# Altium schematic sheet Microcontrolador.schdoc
size 316 x 210 mm
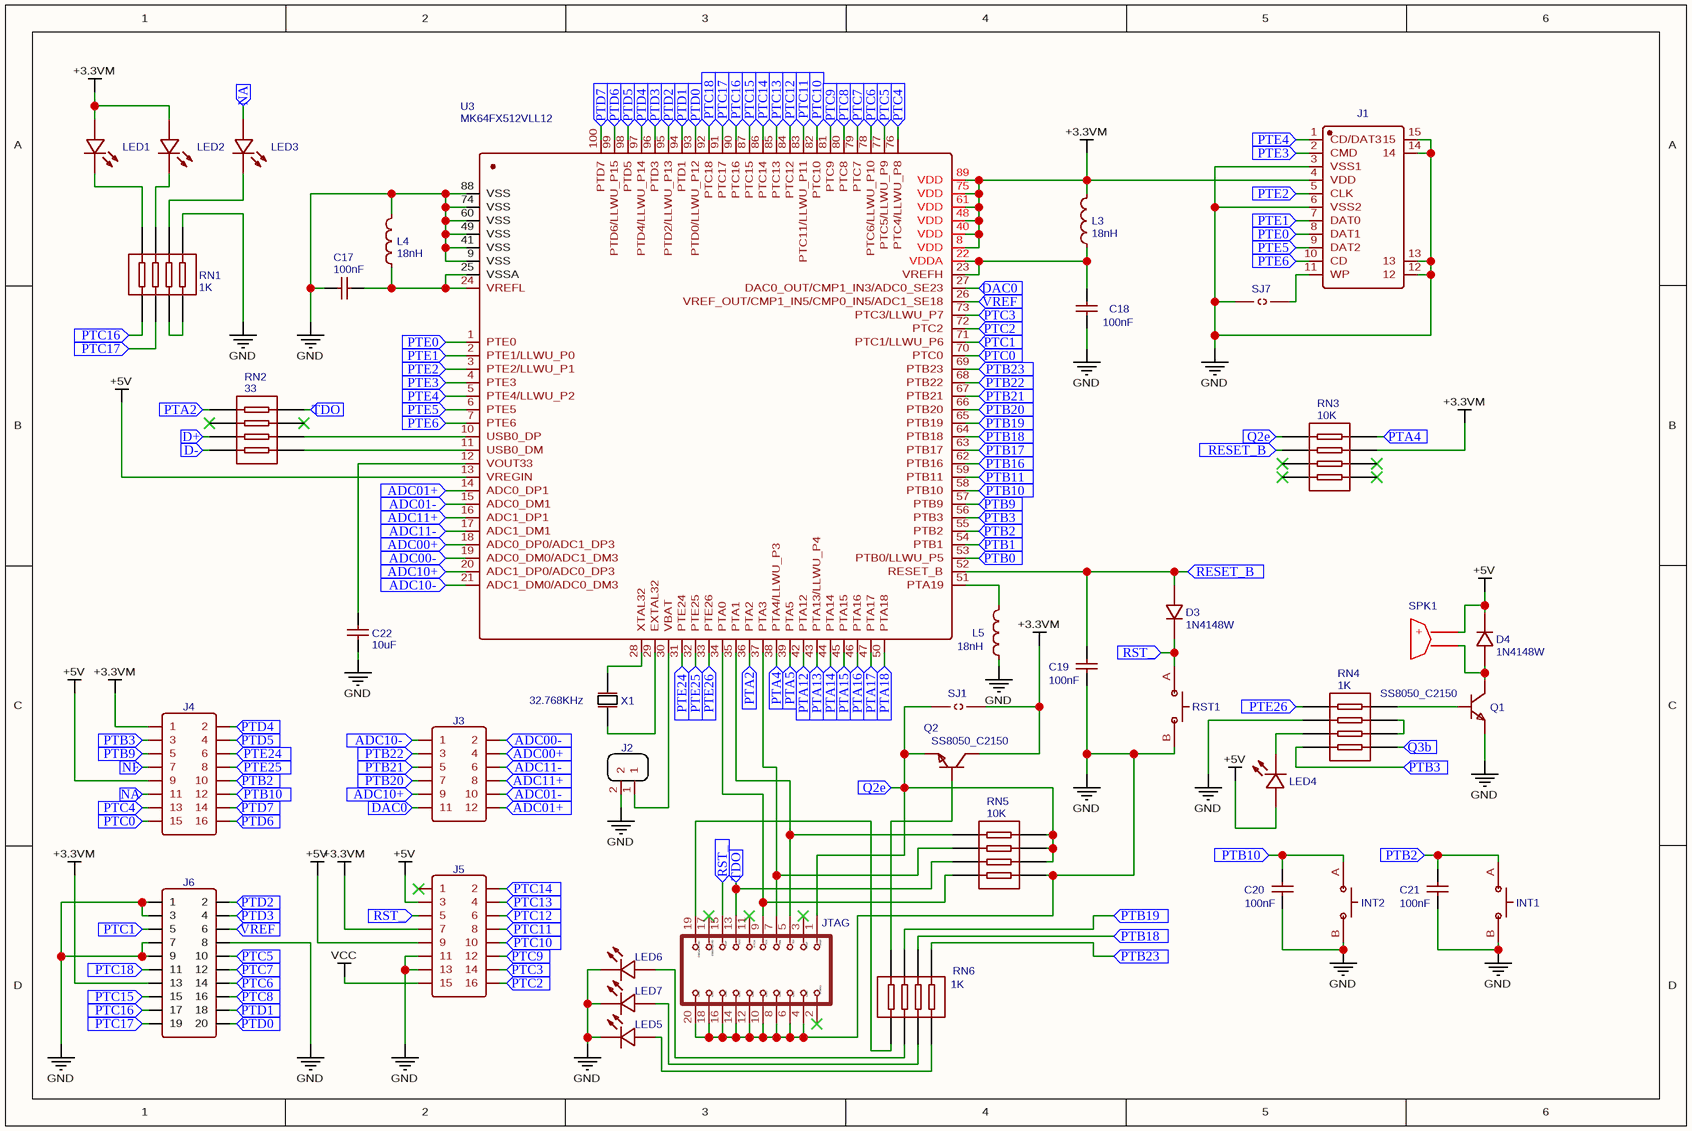
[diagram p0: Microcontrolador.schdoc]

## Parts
C17  100nF  [C0402]
C18  100nF  [C0402]
C19  100nF  [C0402]
C20  100nF  [C0402]
C21  100nF  [C0402]
C22  10uF  [C0805]
D3  1N4148W  [SOD-123_L2.8-W1.8-LS3.7-RD]
D4  1N4148W  [SOD-123_L2.8-W1.8-LS3.7-RD]
INT1  1TS002B-2500-4300 SMD Push  [SW-SMD-3.5X6X4.3-A]  (value not drawn)
INT2  1TS002B-2500-4300 SMD Push  [SW-SMD-3.5X6X4.3-A]  (value not drawn)
J1  HYC12-SD11-275  [SD-SMD_HYC12-SD11-275]  (value not drawn)
J2  53047-02  [MOLEX_53047-0210_2PIN_VERT]  (value not drawn)
J3  HEADER-FEMALE-2.54_2X6 COPY  [HDR-TH_12P-P2.54-V-R2-C6-S2.54]  (value not drawn)
J4  Header-Female-2.54_2x8  [HDR-TH_16P-P2.54-V-R2-C8-S2.54]  (value not drawn)
J5  Header-Female-2.54_2x8  [HDR-TH_16P-P2.54-V-R2-C8-S2.54]  (value not drawn)
J6  HEADER-FEMALE-2.54_2X10  [HDR-TH_20P-P2.54-V-R2-C10-S2.54]  (value not drawn)
JTAG1  JTAG  [2X10_2.54MM_PTH]
L3  18nH  [L0402]
L4  18nH  [L0402]
L5  18nH  [L0402]
LED1  XL-0805QBC  [LED0805-RD]  (value not drawn)
LED2  XL-0805QBC  [LED0805-RD]  (value not drawn)
LED3  XL-0805QBC  [LED0805-RD]  (value not drawn)
LED4  XL-0805QBC  [LED0805-RD]  (value not drawn)
LED5  0603White light_C2290  [LED0603-R-RD]  (value not drawn)
LED6  0603White light_C2290  [LED0603-R-RD]  (value not drawn)
LED7  0603White light_C2290  [LED0603-R-RD]  (value not drawn)
Q1  SS8050_C2150  [SOT-23-3_L2.9-W1.3-P1.90-LS2.4-BR]
Q2  SS8050_C2150  [SOT-23-3_L2.9-W1.3-P1.90-LS2.4-BR]
RN1  1K  [RES-ARRAY-SMD_0402-8P-L2.0-W1.0-BL]
RN2  33  [RES-ARRAY-SMD_0402-8P-L2.0-W1.0-BL]
RN3  10K  [RES-ARRAY-SMD_0402-8P-L2.0-W1.0-BL]
RN4  1K  [RES-ARRAY-SMD_0402-8P-L2.0-W1.0-BL]
RN5  10K  [RES-ARRAY-SMD_0402-8P-L2.0-W1.0-BL]
RN6  1K  [RES-ARRAY-SMD_0402-8P-L2.0-W1.0-BL]
RST1  1TS002B-2500-4300 SMD Push  [SW-SMD-3.5X6X4.3-A]  (value not drawn)
SJ1  JUMPER-PAD-2-NO  [PAD-JUMPER-2-NO_NO_SILK]  (value not drawn)
SJ7  JUMPER-PAD-2-NO  [PAD-JUMPER-2-NO_NO_SILK]  (value not drawn)
SPK1  BUZZER  [BUZZER]  (value not drawn)
U3  MK64FX512VLL12  [LQFP-100_14X14X05P]
X1  32.768KHz  [OSC-TH_BD2.0-P0.70-D0.3]

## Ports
ADC00+ (in), ADC00- (in), ADC01+ (in), ADC01- (in), ADC10+ (in), ADC10- (in), ADC11+ (in), ADC11- (in), D+ (in), D- (in), DAC0 (in), NA (in), NF (in), PTA2 (in), PTA4 (in), PTA5 (in), PTA12 (in), PTA13 (in), PTA14 (in), PTA15 (in), PTA16 (in), PTA17 (in), PTA18 (in), PTB0 (in), PTB1 (in), PTB2 (in), PTB3 (in), PTB9 (in), PTB10 (in), PTB11 (in), PTB16 (in), PTB17 (in), PTB18 (in), PTB19 (in), PTB20 (in), PTB21 (in), PTB22 (in), PTB23 (in), PTC0 (in), PTC1 (in), PTC2 (in), PTC3 (in), PTC4 (in), PTC5 (in), PTC6 (in), PTC7 (in), PTC8 (in), PTC9 (in), PTC10 (in), PTC11 (in), PTC12 (in), PTC13 (in), PTC14 (in), PTC15 (in), PTC16 (in), PTC17 (in), PTC18 (in), PTD0 (in), PTD1 (in), PTD2 (in), PTD3 (in), PTD4 (in), PTD5 (in), PTD6 (in), PTD7 (in), PTE0 (in), PTE1 (in), PTE2 (in), PTE3 (in), PTE4 (in), PTE5 (in), PTE6 (in), PTE24 (in), PTE25 (in), PTE26 (in), Q2e (in), Q3b (in), RESET_B (in), RST_ (in), TDO (in), VREF (in)

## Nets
+3.3VM: J1.4(VDD) J4.1 J5.7 J6.13 L3.2 LED1.2(A) LED2.2(A) Q2.3(C) RN3.7 SJ1.2 U3.8(VDD) U3.40(VDD) U3.48(VDD) U3.61(VDD) U3.75(VDD) U3.89(VDD)
+5V: D4.1(K) J4.9 J5.3 J5.9 LED4.2(A) SPK1.1(+) U3.13(VREGIN)
GND: C17.2 C18.1 C19.1 C20.1 C21.1 C22.1 INT1.B INT2.B J1.3(VSS1) J1.6(VSS2) J1.12 J1.13 J1.14 J1.15 J2.2 J5.11 J5.13 J6.1 J6.3 J6.7 J6.8 J6.9 JTAG1.4 JTAG1.6 JTAG1.8 JTAG1.10 JTAG1.12 JTAG1.14 JTAG1.16 JTAG1.18 JTAG1.20 L4.2 L5.1 LED5.2(K) LED6.2(K) LED7.2(K) Q1.2(E) RN1.5 RN4.6 RN5.5 RST1.B SJ7.1 U3.9(VSS) U3.41(VSS) U3.49(VSS) U3.60(VSS) U3.74(VSS) U3.88(VSS)
VCC: J5.15
ADC00+: J3.4 U3.18(ADC0_DP0/ADC1_DP3) ; port ADC00+
ADC00-: J3.2 U3.19(ADC0_DM0/ADC1_DM3) ; port ADC00-
ADC01+: J3.12 U3.14(ADC0_DP1) ; port ADC01+
ADC01-: J3.10 U3.15(ADC0_DM1) ; port ADC01-
ADC10+: J3.9 U3.20(ADC1_DP0/ADC0_DP3) ; port ADC10+
ADC10-: J3.1 U3.21(ADC1_DM0/ADC0_DM3) ; port ADC10-
ADC11+: J3.8 U3.16(ADC1_DP1) ; port ADC11+
ADC11-: J3.6 U3.17(ADC1_DM1) ; port ADC11-
D+: RN2.3 ; port D+
D-: RN2.4 ; port D-
DAC0: J3.11 U3.27(DAC0_OUT/CMP1_IN3/ADC0_SE23) ; port DAC0
NA: J4.11 LED3.2(A) ; port NA
NF: J4.7 ; port NF
PTA2: RN2.1 U3.36(PTA2) ; port PTA2
PTA4: RN3.8 U3.38(PTA4/LLWU_P3) ; port PTA4
PTA5: U3.39(PTA5) ; port PTA5
PTA12: U3.42(PTA12) ; port PTA12
PTA13: U3.43(PTA13/LLWU_P4) ; port PTA13
PTA14: U3.44(PTA14) ; port PTA14
PTA15: U3.45(PTA15) ; port PTA15
PTA16: U3.46(PTA16) ; port PTA16
PTA17: U3.47(PTA17) ; port PTA17
PTA18: U3.50(PTA18) ; port PTA18
PTB0: U3.53(PTB0/LLWU_P5) ; port PTB0
PTB1: U3.54(PTB1) ; port PTB1
PTB2: C21.2 INT1.A J4.10 U3.55(PTB2) ; port PTB2
PTB3: J4.3 RN4.8 U3.56(PTB3) ; port PTB3
PTB9: J4.5 U3.57(PTB9) ; port PTB9
PTB10: C20.2 INT2.A J4.12 U3.58(PTB10) ; port PTB10
PTB11: U3.59(PTB11) ; port PTB11
PTB16: U3.62(PTB16) ; port PTB16
PTB17: U3.63(PTB17) ; port PTB17
PTB18: RN6.2 U3.64(PTB18) ; port PTB18
PTB19: RN6.3 U3.65(PTB19) ; port PTB19
PTB20: J3.7 U3.66(PTB20) ; port PTB20
PTB21: J3.5 U3.67(PTB21) ; port PTB21
PTB22: J3.3 U3.68(PTB22) ; port PTB22
PTB23: RN6.1 U3.69(PTB23) ; port PTB23
PTC0: J4.15 U3.70(PTC0) ; port PTC0
PTC1: J6.5 U3.71(PTC1/LLWU_P6) ; port PTC1
PTC2: J5.16 U3.72(PTC2) ; port PTC2
PTC3: J5.14 U3.73(PTC3/LLWU_P7) ; port PTC3
PTC4: J4.13 U3.76(PTC4/LLWU_P8) ; port PTC4
PTC5: J6.10 U3.77(PTC5/LLWU_P9) ; port PTC5
PTC6: J6.14 U3.78(PTC6/LLWU_P10) ; port PTC6
PTC7: J6.12 U3.79(PTC7) ; port PTC7
PTC8: J6.16 U3.80(PTC8) ; port PTC8
PTC9: J5.12 U3.81(PTC9) ; port PTC9
PTC10: J5.10 U3.82(PTC10) ; port PTC10
PTC11: J5.8 U3.83(PTC11/LLWU_P11) ; port PTC11
PTC12: J5.6 U3.84(PTC12) ; port PTC12
PTC13: J5.4 U3.85(PTC13) ; port PTC13
PTC14: J5.2 U3.86(PTC14) ; port PTC14
PTC15: J6.15 U3.87(PTC15) ; port PTC15
PTC16: J6.17 RN1.1 U3.90(PTC16) ; port PTC16
PTC17: J6.19 RN1.2 U3.91(PTC17) ; port PTC17
PTC18: J6.11 U3.92(PTC18) ; port PTC18
PTD0: J6.20 U3.93(PTD0/LLWU_P12) ; port PTD0
PTD1: J6.18 U3.94(PTD1) ; port PTD1
PTD2: J6.2 U3.95(PTD2/LLWU_P13) ; port PTD2
PTD3: J6.4 U3.96(PTD3) ; port PTD3
PTD4: J4.2 U3.97(PTD4/LLWU_P14) ; port PTD4
PTD5: J4.4 U3.98(PTD5) ; port PTD5
PTD6: J4.16 U3.99(PTD6/LLWU_P15) ; port PTD6
PTD7: J4.14 U3.100(PTD7) ; port PTD7
PTE0: J1.8(DAT1) U3.1(PTE0) ; port PTE0
PTE1: J1.7(DAT0) U3.2(PTE1/LLWU_P0) ; port PTE1
PTE2: J1.5(CLK) U3.3(PTE2/LLWU_P1) ; port PTE2
PTE3: J1.2(CMD) U3.4(PTE3) ; port PTE3
PTE4: J1.1(CD/DAT3) U3.5(PTE4/LLWU_P2) ; port PTE4
PTE5: J1.9(DAT2) U3.6(PTE5) ; port PTE5
PTE6: J1.10(CD) U3.7(PTE6) ; port PTE6
PTE24: J4.6 U3.31(PTE24) ; port PTE24
PTE25: J4.8 U3.32(PTE25) ; port PTE25
PTE26: RN4.5 U3.33(PTE26) ; port PTE26
Q2e: JTAG1.1 Q2.2(E) RN3.1 RN5.6 RN5.7 RN5.8 SJ1.1 ; port Q2e
Q3b: RN4.1 ; port Q3b
RESET_B: C19.2 D3.2(A) RN3.2 U3.52(RESET_B) ; port RESET_B
RST_: D3.1(K) J5.5 JTAG1.15 RST1.A ; port RST_
TDO: JTAG1.13 RN2.8 RN5.3 ; port TDO
VREF: J6.6 U3.26(VREF_OUT/CMP1_IN5/CMP0_IN5/ADC1_SE18) ; port VREF
NetC17_1: C17.1 L4.1 U3.24(VREFL) U3.25(VSSA)
NetC18_2: C18.2 L3.1 U3.22(VDDA) U3.23(VREFH)
NetC22_2: C22.2 U3.12(VOUT33)
NetD4_2: D4.2(A) Q1.3(C) SPK1.2
NetJ1_11: J1.11(WP) SJ7.2
NetJ2_1: J2.1 U3.30(VBAT)
NetJTAG1_5: JTAG1.5 RN5.1 U3.35(PTA1)
NetJTAG1_7: JTAG1.7 RN5.2 U3.37(PTA3)
NetJTAG1_9: JTAG1.9 RN5.4 U3.34(PTA0)
NetJTAG1_19: JTAG1.19 RN6.5
NetL5_2: L5.2 U3.51(PTA19)
NetLED1_1: LED1.1(K) RN1.8
NetLED2_1: LED2.1(K) RN1.7
NetLED3_1: LED3.1(K) RN1.6
NetLED4_1: LED4.1(K) RN4.7
NetLED5_1: LED5.1(A) RN6.8
NetLED6_1: LED6.1(A) RN6.6
NetLED7_1: LED7.1(A) RN6.7
NetQ1_1: Q1.1(B) RN4.4
NetQ2_1: Q2.1(B) RN6.4
NetRN1_3: RN1.3 RN1.4
NetRN2_5: RN2.5 U3.11(USB0_DM)
NetRN2_6: RN2.6 U3.10(USB0_DP)
NetRN4_2: RN4.2 RN4.3
NetU3_28: U3.28(XTAL32) X1.1(OSC1)
NetU3_29: U3.29(EXTAL32) X1.2(OSC2)

Not connected (* = marked no-connect by the designer): J5 1*; JTAG1 2* 3* 11* 17*; RN2 2* 7*; RN3 3* 4* 5* 6*

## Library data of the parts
C17-C21 = 100nF: BOM_Manufacturer Part: CL05B104KO5NNNC; BOM_Manufacturer: SAMSUNG; nameAlias: Capacitance; SMT Type: Basic; BOM_Paste Type: base
C22 = 10uF: BOM_Manufacturer Part: CL21A106KAYNNNE; BOM_Manufacturer: SAMSUNG; nameAlias: Capacitance; SMT Type: Basic; BOM_Paste Type: base
D3 D4 = 1N4148W: BOM_Manufacturer: SEMTECH; SMT Type: Basic; BOM_Paste Type: base
INT1 INT2 RST1 = 1TS002B-2500-4300 SMD Push: BOM_Manufacturer: HYP; Contributor: LCSC; Package Display: No
J1 = HYC12-SD11-275: BOM_Manufacturer: 华宇创; Contributor: LCSC; Package Display: No
J2 = 53047-02: Contributor: SunWoo_Lim; Package Display: No
J3 = HEADER-FEMALE-2.54_2X6 COPY: BOM_Manufacturer: BOOMELE; Package Display: No
J4 J5 = Header-Female-2.54_2x8: BOM_Manufacturer: BOOMELE; BOM_Manufacturer Part: 2.54mm,2×8Double female header; Contributor: sandiko; Package Display: No
J6 = HEADER-FEMALE-2.54_2X10: BOM_Manufacturer: BOOMELE; BOM_Manufacturer Part: 2.54mm,2×10Double row female; Package Display: No
JTAG1 = JTAG: description: JTAG 20 Pin Programming Connector; Contributor: PatternAgents; Package Display: No
L3-L5 = 18nH: BOM_Manufacturer: Sunlord; BOM_Manufacturer Part: SDCL1005C18NJTDF; nameAlias: Inductance; SMT Type: Basic; BOM_Paste Type: base
LED1-LED4 = XL-0805QBC: BOM_Manufacturer: KENTO; SMT Type: Basic; BOM_Paste Type: base; Package Display: No
LED5-LED7 = 0603White light_C2290: BOM_Manufacturer: KENTO; SMT Type: Basic; BOM_Paste Type: base; Package Display: No
Q1 Q2 = SS8050_C2150: BOM_Manufacturer: CJ; BOM_Manufacturer Part: SS8050; SMT Type: Basic; BOM_Assembly Type: smtWeld; BOM_Paste Type: base
RN1 RN4 RN6 = 1K: BOM_Manufacturer: UniOhm; BOM_Manufacturer Part: 4D02WGJ0102TCE; nameAlias: Resistance (Ohms); SMT Type: Basic; BOM_Paste Type: base
RN2 = 33: BOM_Manufacturer: UniOhm; BOM_Manufacturer Part: 4D02WGJ0330TCE; nameAlias: Resistance (Ohms); SMT Type: Basic; BOM_Assembly Type: smtWeld; BOM_Paste Type: base
RN3 RN5 = 10K: BOM_Manufacturer: UniOhm; BOM_Manufacturer Part: 4D02WGJ0103TCE; nameAlias: Resistance (Ohms); SMT Type: Basic; BOM_Paste Type: base
SJ1 SJ7 = JUMPER-PAD-2-NO: Contributor: SparkFun; Package Display: No
SPK1 = BUZZER: Contributor: P3-102; Package Display: No
U3 = MK64FX512VLL12: Package Display: No
X1 = 32.768KHz: BOM_Manufacturer: CITIZEN; BOM_Manufacturer Part: CFS20632768DZBB; Contributor: LCSC; Package Display: No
